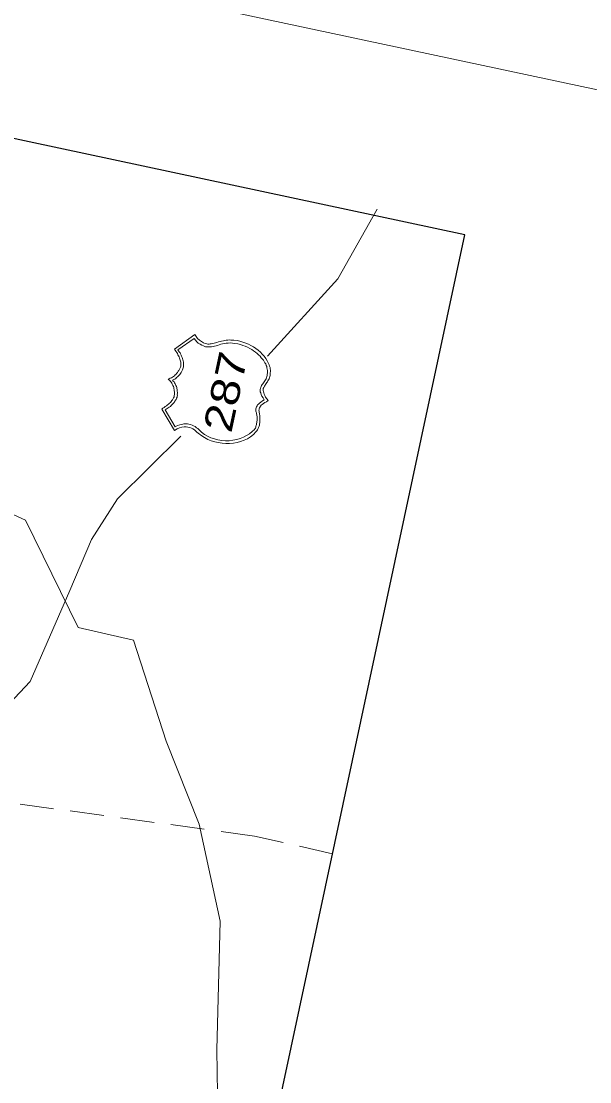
# Model space of a CAD drawing. Extents: x 2363411 to 2369126, y 6976878 to 6988319.
# Drawn here: x 2366148.5 to 2366249.3, y 6977167 to 6977355.3 of the extents above; entities that cross this region are included whole.
import ezdxf

# ---------------------------------------------------------------- set-up
doc = ezdxf.new("R2010")
doc.units = 0
doc.header["$LTSCALE"] = 2
doc.linetypes.add('MEDIUM_DASHED', pattern=[4.5, 3, -1.5])
for name, color, linetype, lineweight in [('44', 7, 'Continuous', 40), ('62', 7, 'Continuous', 13), ('63', 7, 'Continuous', 13)]:
    doc.layers.add(name, color=color, linetype=linetype, lineweight=lineweight)

msp = doc.modelspace()

# ---------------------------------------------------------------- linework, layer by layer
at = {"layer": '44', "lineweight": 13}
msp.add_line((2363411.416, 6977949.748), (2366932.108, 6977197.487), dxfattribs=at)
at = {"layer": '62'}
for p, q in [((2366211.587, 6977321.915), (2366204.664, 6977309.563)), ((2366204.664, 6977309.563), (2366192.137, 6977295.834)), ((2366165.563, 6977270.54), (2366176.769, 6977281.631))]:
    msp.add_line(p, q, dxfattribs=at)
at = {"layer": '62', "lineweight": 25}
msp.add_lwpolyline([(2365678.211, 6976974.92), (2366133.213, 6976877.7), (2366227.156, 6977317.368), (2365772.152, 6977414.588)], dxfattribs=at)
at = {"layer": '62'}
for points in [[(2366096.932, 6977302.67), (2366104.486, 6977295.374), (2366118.795, 6977282.65), (2366135.856, 6977272.793), (2366149.213, 6977266.718), (2366158.553, 6977247.649), (2366168.364, 6977245.412), (2366174.148, 6977227.473), (2366180.022, 6977212.757), (2366183.73, 6977195.536), (2366183.185, 6977172.733), (2366183.468, 6977153.162), (2366184.402, 6977131.701), (2366184.733, 6977118.813)], [(2366175.627, 6977282.636), (2366173.381, 6977286.45), (2366173.595, 6977286.59), (2366173.831, 6977286.722), (2366174.026, 6977286.886), (2366174.236, 6977287.003), (2366174.432, 6977287.172), (2366174.603, 6977287.317), (2366174.771, 6977287.466), (2366174.946, 6977287.635), (2366175.068, 6977287.77), (2366175.197, 6977287.949), (2366175.324, 6977288.106), (2366175.411, 6977288.296), (2366175.492, 6977288.463), (2366175.566, 6977288.607), (2366175.616, 6977288.827), (2366175.658, 6977289.025), (2366175.642, 6977289.167), (2366175.629, 6977289.329), (2366175.645, 6977289.51), (2366175.617, 6977289.7), (2366175.589, 6977289.892), (2366175.534, 6977290.064), (2366175.506, 6977290.256), (2366175.456, 6977290.448), (2366175.357, 6977290.631), (2366175.263, 6977290.835), (2366175.164, 6977291.018), (2366175.087, 6977291.194), (2366174.954, 6977291.339), (2366174.83, 6977291.502), (2366174.646, 6977291.611), (2366174.515, 6977291.754), (2366174.691, 6977291.831), (2366174.914, 6977291.9), (2366175.118, 6977291.993), (2366175.28, 6977292.097), (2366175.467, 6977292.219), (2366175.636, 6977292.365), (2366175.777, 6977292.496), (2366175.926, 6977292.649), (2366176.072, 6977292.799), (2366176.215, 6977292.932), (2366176.308, 6977293.142), (2366176.428, 6977293.28), (2366176.525, 6977293.511), (2366176.601, 6977293.656), (2366176.693, 6977293.865), (2366176.752, 6977294.039), (2366176.784, 6977294.191), (2366176.803, 6977294.394), (2366176.767, 6977294.541), (2366176.766, 6977294.745), (2366176.736, 6977294.938), (2366176.681, 6977295.111), (2366176.628, 6977295.284), (2366176.558, 6977295.506), (2366176.459, 6977295.688), (2366176.388, 6977295.886), (2366176.266, 6977296.073), (2366176.176, 6977296.299), (2366176.057, 6977296.488), (2366175.916, 6977296.7), (2366175.773, 6977296.892), (2366175.657, 6977297.101), (2366179.266, 6977299.668), (2366179.513, 6977299.314), (2366179.759, 6977298.963), (2366180.09, 6977298.684), (2366180.454, 6977298.446), (2366180.796, 6977298.212), (2366181.111, 6977298.073), (2366181.397, 6977298.014), (2366181.595, 6977297.972), (2366181.782, 6977297.979), (2366181.992, 6977298.003), (2366182.184, 6977298.03), (2366182.422, 6977298.071), (2366182.664, 6977298.134), (2366182.909, 6977298.198), (2366183.179, 6977298.279), (2366183.449, 6977298.359), (2366183.743, 6977298.433), (2366184.012, 6977298.515), (2366184.323, 6977298.563), (2366184.588, 6977298.62), (2366184.849, 6977298.657), (2366185.108, 6977298.693), (2366185.387, 6977298.703), (2366185.637, 6977298.695), (2366186.203, 6977298.644), (2366186.768, 6977298.594), (2366187.273, 6977298.484), (2366187.786, 6977298.305), (2366188.305, 6977298.149), (2366188.772, 6977297.958), (2366189.227, 6977297.721), (2366189.677, 6977297.464), (2366190.106, 6977297.212), (2366190.522, 6977296.892)], [(2366191.02, 6977295.567), (2366190.844, 6977295.811), (2366190.573, 6977296.055), (2366190.303, 6977296.295), (2366190.01, 6977296.542), (2366189.692, 6977296.771), (2366189.35, 6977297.006), (2366189.005, 6977297.219), (2366188.608, 6977297.416), (2366188.193, 6977297.621), (2366187.784, 6977297.754), (2366187.336, 6977297.917), (2366186.873, 6977298.02), (2366186.386, 6977298.099), (2366185.957, 6977298.144), (2366185.553, 6977298.185), (2366185.2, 6977298.146), (2366184.829, 6977298.131), (2366184.491, 6977298.067), (2366184.182, 6977298.018), (2366183.868, 6977297.946), (2366183.572, 6977297.848), (2366183.274, 6977297.752), (2366183.025, 6977297.666), (2366182.76, 6977297.608), (2366182.495, 6977297.55), (2366182.208, 6977297.495), (2366181.974, 6977297.477), (2366181.716, 6977297.463), (2366181.443, 6977297.474), (2366181.13, 6977297.519), (2366180.814, 6977297.656), (2366180.498, 6977297.793), (2366180.187, 6977297.951), (2366179.864, 6977298.157), (2366179.615, 6977298.395), (2366179.375, 6977298.677), (2366179.136, 6977298.957), (2366176.246, 6977296.953), (2366176.368, 6977296.767), (2366176.494, 6977296.599), (2366176.637, 6977296.409), (2366176.737, 6977296.226), (2366176.852, 6977296.019), (2366176.924, 6977295.818), (2366176.997, 6977295.62), (2366177.07, 6977295.419), (2366177.137, 6977295.198), (2366177.209, 6977294.998), (2366177.233, 6977294.785), (2366177.239, 6977294.601), (2366177.269, 6977294.409), (2366177.257, 6977294.252), (2366177.247, 6977294.095), (2366177.237, 6977293.933), (2366177.181, 6977293.786), (2366177.12, 6977293.612), (2366177.079, 6977293.417), (2366177.001, 6977293.27), (2366176.888, 6977293.065), (2366176.812, 6977292.92), (2366176.707, 6977292.758), (2366176.579, 6977292.579), (2366176.456, 6977292.443), (2366176.326, 6977292.265), (2366176.189, 6977292.157), (2366176.022, 6977292.031), (2366175.875, 6977291.878), (2366175.693, 6977291.78), (2366175.512, 6977291.68), (2366175.307, 6977291.587), (2366175.432, 6977291.421), (2366175.58, 6977291.252), (2366175.662, 6977291.095), (2366175.766, 6977290.934), (2366175.821, 6977290.763), (2366175.907, 6977290.628), (2366175.981, 6977290.428), (2366176.04, 6977290.279), (2366176.074, 6977290.11), (2366176.125, 6977289.915), (2366176.14, 6977289.772), (2366176.145, 6977289.589), (2366176.157, 6977289.425), (2366176.19, 6977289.256), (2366176.152, 6977289.081), (2366176.163, 6977288.919), (2366176.153, 6977288.757), (2366176.105, 6977288.539), (2366175.997, 6977288.355), (2366175.927, 6977288.139), (2366175.801, 6977287.982), (2366175.69, 6977287.774), (2366175.554, 6977287.576), (2366175.41, 6977287.443), (2366175.254, 6977287.248), (2366175.08, 6977287.078), (2366174.932, 6977286.926), (2366174.721, 6977286.807), (2366174.549, 6977286.64), (2366174.34, 6977286.521)], [(2366174.02, 6977286.315), (2366175.794, 6977283.312), (2366176.204, 6977283.501), (2366176.603, 6977283.644), (2366176.965, 6977283.729), (2366177.305, 6977283.818), (2366177.649, 6977283.812), (2366177.949, 6977283.817), (2366178.217, 6977283.782), (2366178.522, 6977283.697), (2366178.795, 6977283.569), (2366179.048, 6977283.468), (2366179.295, 6977283.323), (2366179.531, 6977283.133), (2366179.77, 6977282.97), (2366180.005, 6977282.78), (2366180.216, 6977282.576), (2366180.446, 6977282.363), (2366180.956, 6977281.956), (2366181.532, 6977281.626), (2366182.092, 6977281.345), (2366182.737, 6977281.137), (2366183.371, 6977280.979), (2366184.035, 6977280.86), (2366184.72, 6977280.828), (2366185.364, 6977280.83), (2366186.022, 6977280.895), (2366186.695, 6977281.028), (2366187.313, 6977281.219), (2366187.911, 6977281.437), (2366188.455, 6977281.734), (2366188.985, 6977282.058), (2366189.437, 6977282.444), (2366189.843, 6977282.84), (2366189.91, 6977282.94), (2366190.006, 6977283.059), (2366190.059, 6977283.209), (2366190.097, 6977283.385), (2366190.147, 6977283.511), (2366190.186, 6977283.689), (2366190.224, 6977283.865), (2366190.261, 6977284.041), (2366190.282, 6977284.243), (2366190.313, 6977284.398), (2366190.313, 6977284.603), (2366190.327, 6977284.786), (2366190.318, 6977284.949), (2366190.311, 6977285.135), (2366190.277, 6977285.304), (2366190.283, 6977285.44), (2366190.224, 6977285.591), (2366190.189, 6977285.758), (2366190.15, 6977285.883), (2366190.114, 6977286.05), (2366190.104, 6977286.214), (2366190.111, 6977286.352), (2366190.1, 6977286.513), (2366190.131, 6977286.668), (2366190.208, 6977286.813), (2366190.295, 6977287.004), (2366190.376, 6977287.168), (2366190.545, 6977287.314), (2366190.725, 6977287.509), (2366190.992, 6977287.681), (2366191.268, 6977287.898), (2366191.585, 6977288.084), (2366191.359, 6977288.431), (2366191.174, 6977288.746), (2366191.05, 6977289.024), (2366190.948, 6977289.302), (2366190.879, 6977289.523), (2366190.878, 6977289.73), (2366190.871, 6977289.915), (2366190.918, 6977290.136), (2366190.951, 6977290.291), (2366191.028, 6977290.434), (2366191.114, 6977290.622), (2366191.217, 6977290.784), (2366191.339, 6977290.922), (2366191.441, 6977291.082), (2366191.552, 6977291.265), (2366191.683, 6977291.446), (2366191.791, 6977291.629), (2366191.897, 6977291.811), (2366191.963, 6977292.005), (2366192.009, 6977292.227), (2366192.074, 6977292.421), (2366192.1, 6977292.645), (2366192.141, 6977292.843), (2366192.144, 6977293.071), (2366192.148, 6977293.301), (2366192.124, 6977293.513), (2366192.061, 6977293.758), (2366192.015, 6977293.974), (2366191.925, 6977294.2), (2366191.841, 6977294.449), (2366191.702, 6977294.663), (2366191.545, 6977294.903), (2366191.43, 6977295.111), (2366191.225, 6977295.339), (2366191.02, 6977295.567)], [(2366190.522, 6977296.892), (2366190.887, 6977296.561), (2366191.201, 6977296.195), (2366191.564, 6977295.842), (2366191.834, 6977295.391), (2366192.117, 6977294.987), (2366192.341, 6977294.526), (2366192.447, 6977294.272), (2366192.537, 6977294.049), (2366192.599, 6977293.802), (2366192.64, 6977293.564), (2366192.687, 6977293.348), (2366192.661, 6977293.122), (2366192.655, 6977292.87), (2366192.655, 6977292.665), (2366192.603, 6977292.421), (2366192.556, 6977292.2), (2366192.491, 6977292.009), (2366192.432, 6977291.838), (2366192.319, 6977291.633), (2366192.238, 6977291.464), (2366192.157, 6977291.297), (2366192.03, 6977291.14), (2366191.927, 6977290.98), (2366191.824, 6977290.816), (2366191.729, 6977290.7), (2366191.627, 6977290.537), (2366191.575, 6977290.409), (2366191.493, 6977290.243), (2366191.412, 6977290.078), (2366191.402, 6977289.917), (2366191.409, 6977289.731), (2366191.431, 6977289.52), (2366191.504, 6977289.32), (2366191.571, 6977289.099), (2366191.678, 6977288.845), (2366191.829, 6977288.584), (2366192.041, 6977288.285), (2366192.27, 6977287.96), (2366191.95, 6977287.75), (2366191.684, 6977287.58), (2366191.421, 6977287.428), (2366191.22, 6977287.241), (2366191.057, 6977287.115), (2366190.932, 6977286.958), (2366190.83, 6977286.818), (2366190.755, 6977286.674), (2366190.703, 6977286.546), (2366190.671, 6977286.391), (2366190.643, 6977286.26), (2366190.654, 6977286.099), (2366190.674, 6977285.98), (2366190.664, 6977285.818), (2366190.719, 6977285.647), (2366190.734, 6977285.505), (2366190.772, 6977285.36), (2366190.784, 6977285.195), (2366190.811, 6977285.006), (2366190.813, 6977284.797), (2366190.819, 6977284.611), (2366190.799, 6977284.409), (2366190.803, 6977284.202), (2366190.809, 6977284.018), (2366190.76, 6977283.798), (2366190.718, 6977283.598), (2366190.676, 6977283.398), (2366190.582, 6977283.167), (2366190.494, 6977282.977), (2366190.381, 6977282.772), (2366190.246, 6977282.572), (2366190.088, 6977282.375), (2366189.65, 6977281.938), (2366189.128, 6977281.543), (2366188.59, 6977281.175), (2366188.003, 6977280.91), (2366187.38, 6977280.675), (2366186.745, 6977280.512), (2366186.105, 6977280.42), (2366185.424, 6977280.357), (2366184.754, 6977280.338), (2366184.096, 6977280.387), (2366183.426, 6977280.485), (2366182.787, 6977280.619), (2366182.162, 6977280.823), (2366181.574, 6977281.065), (2366180.993, 6977281.373), (2366180.49, 6977281.709), (2366180.288, 6977281.845), (2366180.07, 6977282.006), (2366179.878, 6977282.186), (2366179.644, 6977282.373), (2366179.409, 6977282.564), (2366179.173, 6977282.75), (2366178.931, 6977282.918), (2366178.66, 6977283.043), (2366178.366, 6977283.176), (2366178.035, 6977283.248), (2366177.701, 6977283.295), (2366177.351, 6977283.278), (2366176.949, 6977283.227), (2366176.533, 6977283.107)], [(2366174.34, 6977286.521), (2366174.181, 6977286.418), (2366174.02, 6977286.315)], [(2366176.533, 6977283.107), (2366176.103, 6977282.923), (2366175.627, 6977282.636)], [(2366165.563, 6977270.54), (2366160.925, 6977263.273), (2366157.11, 6977254.238), (2366150.016, 6977238.06), (2366141.756, 6977229.335), (2366136.001, 6977223.497), (2366128.351, 6977216.018), (2366117.334, 6977209.377), (2366106.082, 6977205.501), (2366093.663, 6977202.078), (2366078.646, 6977196.636), (2366068.712, 6977191.165), (2366059.206, 6977187.374), (2366047.443, 6977183.467), (2366041.833, 6977180.594), (2366027.902, 6977176.345)]]:
    msp.add_lwpolyline(points, dxfattribs=at)
at = {"layer": '62', "linetype": 'MEDIUM_DASHED'}
msp.add_lwpolyline([(2366203.686, 6977207.519), (2366189.861, 6977210.657), (2366146.236, 6977216.593), (2366117.386, 6977222.114)], dxfattribs=at)
at = {"layer": '63'}
for p, q in [((2366211.587, 6977321.915), (2366204.664, 6977309.563)), ((2366204.664, 6977309.563), (2366192.137, 6977295.834)), ((2366165.563, 6977270.54), (2366176.769, 6977281.631))]:
    msp.add_line(p, q, dxfattribs=at)
at = {"layer": '63', "lineweight": 25}
msp.add_lwpolyline([(2365678.211, 6976974.92), (2366133.213, 6976877.7), (2366227.156, 6977317.368), (2365772.152, 6977414.588)], dxfattribs=at)
at = {"layer": '63'}
for points in [[(2366096.932, 6977302.67), (2366104.486, 6977295.374), (2366118.795, 6977282.65), (2366135.856, 6977272.793), (2366149.213, 6977266.718), (2366158.553, 6977247.649), (2366168.364, 6977245.412), (2366174.148, 6977227.473), (2366180.022, 6977212.757), (2366183.73, 6977195.536), (2366183.185, 6977172.733), (2366183.468, 6977153.162), (2366184.402, 6977131.701), (2366184.733, 6977118.813)], [(2366175.627, 6977282.636), (2366173.381, 6977286.45), (2366173.595, 6977286.59), (2366173.831, 6977286.722), (2366174.026, 6977286.886), (2366174.236, 6977287.003), (2366174.432, 6977287.172), (2366174.603, 6977287.317), (2366174.771, 6977287.466), (2366174.946, 6977287.635), (2366175.068, 6977287.77), (2366175.197, 6977287.949), (2366175.324, 6977288.106), (2366175.411, 6977288.296), (2366175.492, 6977288.463), (2366175.566, 6977288.607), (2366175.616, 6977288.827), (2366175.658, 6977289.025), (2366175.642, 6977289.167), (2366175.629, 6977289.329), (2366175.645, 6977289.51), (2366175.617, 6977289.7), (2366175.589, 6977289.892), (2366175.534, 6977290.064), (2366175.506, 6977290.256), (2366175.456, 6977290.448), (2366175.357, 6977290.631), (2366175.263, 6977290.835), (2366175.164, 6977291.018), (2366175.087, 6977291.194), (2366174.954, 6977291.339), (2366174.83, 6977291.502), (2366174.646, 6977291.611), (2366174.515, 6977291.754), (2366174.691, 6977291.831), (2366174.914, 6977291.9), (2366175.118, 6977291.993), (2366175.28, 6977292.097), (2366175.467, 6977292.219), (2366175.636, 6977292.365), (2366175.777, 6977292.496), (2366175.926, 6977292.649), (2366176.072, 6977292.799), (2366176.215, 6977292.932), (2366176.308, 6977293.142), (2366176.428, 6977293.28), (2366176.525, 6977293.511), (2366176.601, 6977293.656), (2366176.693, 6977293.865), (2366176.752, 6977294.039), (2366176.784, 6977294.191), (2366176.803, 6977294.394), (2366176.767, 6977294.541), (2366176.766, 6977294.745), (2366176.736, 6977294.938), (2366176.681, 6977295.111), (2366176.628, 6977295.284), (2366176.558, 6977295.506), (2366176.459, 6977295.688), (2366176.388, 6977295.886), (2366176.266, 6977296.073), (2366176.176, 6977296.299), (2366176.057, 6977296.488), (2366175.916, 6977296.7), (2366175.773, 6977296.892), (2366175.657, 6977297.101), (2366179.266, 6977299.668), (2366179.513, 6977299.314), (2366179.759, 6977298.963), (2366180.09, 6977298.684), (2366180.454, 6977298.446), (2366180.796, 6977298.212), (2366181.111, 6977298.073), (2366181.397, 6977298.014), (2366181.595, 6977297.972), (2366181.782, 6977297.979), (2366181.992, 6977298.003), (2366182.184, 6977298.03), (2366182.422, 6977298.071), (2366182.664, 6977298.134), (2366182.909, 6977298.198), (2366183.179, 6977298.279), (2366183.449, 6977298.359), (2366183.743, 6977298.433), (2366184.012, 6977298.515), (2366184.323, 6977298.563), (2366184.588, 6977298.62), (2366184.849, 6977298.657), (2366185.108, 6977298.693), (2366185.387, 6977298.703), (2366185.637, 6977298.695), (2366186.203, 6977298.644), (2366186.768, 6977298.594), (2366187.273, 6977298.484), (2366187.786, 6977298.305), (2366188.305, 6977298.149), (2366188.772, 6977297.958), (2366189.227, 6977297.721), (2366189.677, 6977297.464), (2366190.106, 6977297.212), (2366190.522, 6977296.892)], [(2366191.02, 6977295.567), (2366190.844, 6977295.811), (2366190.573, 6977296.055), (2366190.303, 6977296.295), (2366190.01, 6977296.542), (2366189.692, 6977296.771), (2366189.35, 6977297.006), (2366189.005, 6977297.219), (2366188.608, 6977297.416), (2366188.193, 6977297.621), (2366187.784, 6977297.754), (2366187.336, 6977297.917), (2366186.873, 6977298.02), (2366186.386, 6977298.099), (2366185.957, 6977298.144), (2366185.553, 6977298.185), (2366185.2, 6977298.146), (2366184.829, 6977298.131), (2366184.491, 6977298.067), (2366184.182, 6977298.018), (2366183.868, 6977297.946), (2366183.572, 6977297.848), (2366183.274, 6977297.752), (2366183.025, 6977297.666), (2366182.76, 6977297.608), (2366182.495, 6977297.55), (2366182.208, 6977297.495), (2366181.974, 6977297.477), (2366181.716, 6977297.463), (2366181.443, 6977297.474), (2366181.13, 6977297.519), (2366180.814, 6977297.656), (2366180.498, 6977297.793), (2366180.187, 6977297.951), (2366179.864, 6977298.157), (2366179.615, 6977298.395), (2366179.375, 6977298.677), (2366179.136, 6977298.957), (2366176.246, 6977296.953), (2366176.368, 6977296.767), (2366176.494, 6977296.599), (2366176.637, 6977296.409), (2366176.737, 6977296.226), (2366176.852, 6977296.019), (2366176.924, 6977295.818), (2366176.997, 6977295.62), (2366177.07, 6977295.419), (2366177.137, 6977295.198), (2366177.209, 6977294.998), (2366177.233, 6977294.785), (2366177.239, 6977294.601), (2366177.269, 6977294.409), (2366177.257, 6977294.252), (2366177.247, 6977294.095), (2366177.237, 6977293.933), (2366177.181, 6977293.786), (2366177.12, 6977293.612), (2366177.079, 6977293.417), (2366177.001, 6977293.27), (2366176.888, 6977293.065), (2366176.812, 6977292.92), (2366176.707, 6977292.758), (2366176.579, 6977292.579), (2366176.456, 6977292.443), (2366176.326, 6977292.265), (2366176.189, 6977292.157), (2366176.022, 6977292.031), (2366175.875, 6977291.878), (2366175.693, 6977291.78), (2366175.512, 6977291.68), (2366175.307, 6977291.587), (2366175.432, 6977291.421), (2366175.58, 6977291.252), (2366175.662, 6977291.095), (2366175.766, 6977290.934), (2366175.821, 6977290.763), (2366175.907, 6977290.628), (2366175.981, 6977290.428), (2366176.04, 6977290.279), (2366176.074, 6977290.11), (2366176.125, 6977289.915), (2366176.14, 6977289.772), (2366176.145, 6977289.589), (2366176.157, 6977289.425), (2366176.19, 6977289.256), (2366176.152, 6977289.081), (2366176.163, 6977288.919), (2366176.153, 6977288.757), (2366176.105, 6977288.539), (2366175.997, 6977288.355), (2366175.927, 6977288.139), (2366175.801, 6977287.982), (2366175.69, 6977287.774), (2366175.554, 6977287.576), (2366175.41, 6977287.443), (2366175.254, 6977287.248), (2366175.08, 6977287.078), (2366174.932, 6977286.926), (2366174.721, 6977286.807), (2366174.549, 6977286.64), (2366174.34, 6977286.521)], [(2366174.02, 6977286.315), (2366175.794, 6977283.312), (2366176.204, 6977283.501), (2366176.603, 6977283.644), (2366176.965, 6977283.729), (2366177.305, 6977283.818), (2366177.649, 6977283.812), (2366177.949, 6977283.817), (2366178.217, 6977283.782), (2366178.522, 6977283.697), (2366178.795, 6977283.569), (2366179.048, 6977283.468), (2366179.295, 6977283.323), (2366179.531, 6977283.133), (2366179.77, 6977282.97), (2366180.005, 6977282.78), (2366180.216, 6977282.576), (2366180.446, 6977282.363), (2366180.956, 6977281.956), (2366181.532, 6977281.626), (2366182.092, 6977281.345), (2366182.737, 6977281.137), (2366183.371, 6977280.979), (2366184.035, 6977280.86), (2366184.72, 6977280.828), (2366185.364, 6977280.83), (2366186.022, 6977280.895), (2366186.695, 6977281.028), (2366187.313, 6977281.219), (2366187.911, 6977281.437), (2366188.455, 6977281.734), (2366188.985, 6977282.058), (2366189.437, 6977282.444), (2366189.843, 6977282.84), (2366189.91, 6977282.94), (2366190.006, 6977283.059), (2366190.059, 6977283.209), (2366190.097, 6977283.385), (2366190.147, 6977283.511), (2366190.186, 6977283.689), (2366190.224, 6977283.865), (2366190.261, 6977284.041), (2366190.282, 6977284.243), (2366190.313, 6977284.398), (2366190.313, 6977284.603), (2366190.327, 6977284.786), (2366190.318, 6977284.949), (2366190.311, 6977285.135), (2366190.277, 6977285.304), (2366190.283, 6977285.44), (2366190.224, 6977285.591), (2366190.189, 6977285.758), (2366190.15, 6977285.883), (2366190.114, 6977286.05), (2366190.104, 6977286.214), (2366190.111, 6977286.352), (2366190.1, 6977286.513), (2366190.131, 6977286.668), (2366190.208, 6977286.813), (2366190.295, 6977287.004), (2366190.376, 6977287.168), (2366190.545, 6977287.314), (2366190.725, 6977287.509), (2366190.992, 6977287.681), (2366191.268, 6977287.898), (2366191.585, 6977288.084), (2366191.359, 6977288.431), (2366191.174, 6977288.746), (2366191.05, 6977289.024), (2366190.948, 6977289.302), (2366190.879, 6977289.523), (2366190.878, 6977289.73), (2366190.871, 6977289.915), (2366190.918, 6977290.136), (2366190.951, 6977290.291), (2366191.028, 6977290.434), (2366191.114, 6977290.622), (2366191.217, 6977290.784), (2366191.339, 6977290.922), (2366191.441, 6977291.082), (2366191.552, 6977291.265), (2366191.683, 6977291.446), (2366191.791, 6977291.629), (2366191.897, 6977291.811), (2366191.963, 6977292.005), (2366192.009, 6977292.227), (2366192.074, 6977292.421), (2366192.1, 6977292.645), (2366192.141, 6977292.843), (2366192.144, 6977293.071), (2366192.148, 6977293.301), (2366192.124, 6977293.513), (2366192.061, 6977293.758), (2366192.015, 6977293.974), (2366191.925, 6977294.2), (2366191.841, 6977294.449), (2366191.702, 6977294.663), (2366191.545, 6977294.903), (2366191.43, 6977295.111), (2366191.225, 6977295.339), (2366191.02, 6977295.567)], [(2366190.522, 6977296.892), (2366190.887, 6977296.561), (2366191.201, 6977296.195), (2366191.564, 6977295.842), (2366191.834, 6977295.391), (2366192.117, 6977294.987), (2366192.341, 6977294.526), (2366192.447, 6977294.272), (2366192.537, 6977294.049), (2366192.599, 6977293.802), (2366192.64, 6977293.564), (2366192.687, 6977293.348), (2366192.661, 6977293.122), (2366192.655, 6977292.87), (2366192.655, 6977292.665), (2366192.603, 6977292.421), (2366192.556, 6977292.2), (2366192.491, 6977292.009), (2366192.432, 6977291.838), (2366192.319, 6977291.633), (2366192.238, 6977291.464), (2366192.157, 6977291.297), (2366192.03, 6977291.14), (2366191.927, 6977290.98), (2366191.824, 6977290.816), (2366191.729, 6977290.7), (2366191.627, 6977290.537), (2366191.575, 6977290.409), (2366191.493, 6977290.243), (2366191.412, 6977290.078), (2366191.402, 6977289.917), (2366191.409, 6977289.731), (2366191.431, 6977289.52), (2366191.504, 6977289.32), (2366191.571, 6977289.099), (2366191.678, 6977288.845), (2366191.829, 6977288.584), (2366192.041, 6977288.285), (2366192.27, 6977287.96), (2366191.95, 6977287.75), (2366191.684, 6977287.58), (2366191.421, 6977287.428), (2366191.22, 6977287.241), (2366191.057, 6977287.115), (2366190.932, 6977286.958), (2366190.83, 6977286.818), (2366190.755, 6977286.674), (2366190.703, 6977286.546), (2366190.671, 6977286.391), (2366190.643, 6977286.26), (2366190.654, 6977286.099), (2366190.674, 6977285.98), (2366190.664, 6977285.818), (2366190.719, 6977285.647), (2366190.734, 6977285.505), (2366190.772, 6977285.36), (2366190.784, 6977285.195), (2366190.811, 6977285.006), (2366190.813, 6977284.797), (2366190.819, 6977284.611), (2366190.799, 6977284.409), (2366190.803, 6977284.202), (2366190.809, 6977284.018), (2366190.76, 6977283.798), (2366190.718, 6977283.598), (2366190.676, 6977283.398), (2366190.582, 6977283.167), (2366190.494, 6977282.977), (2366190.381, 6977282.772), (2366190.246, 6977282.572), (2366190.088, 6977282.375), (2366189.65, 6977281.938), (2366189.128, 6977281.543), (2366188.59, 6977281.175), (2366188.003, 6977280.91), (2366187.38, 6977280.675), (2366186.745, 6977280.512), (2366186.105, 6977280.42), (2366185.424, 6977280.357), (2366184.754, 6977280.338), (2366184.096, 6977280.387), (2366183.426, 6977280.485), (2366182.787, 6977280.619), (2366182.162, 6977280.823), (2366181.574, 6977281.065), (2366180.993, 6977281.373), (2366180.49, 6977281.709), (2366180.288, 6977281.845), (2366180.07, 6977282.006), (2366179.878, 6977282.186), (2366179.644, 6977282.373), (2366179.409, 6977282.564), (2366179.173, 6977282.75), (2366178.931, 6977282.918), (2366178.66, 6977283.043), (2366178.366, 6977283.176), (2366178.035, 6977283.248), (2366177.701, 6977283.295), (2366177.351, 6977283.278), (2366176.949, 6977283.227), (2366176.533, 6977283.107)], [(2366174.34, 6977286.521), (2366174.181, 6977286.418), (2366174.02, 6977286.315)], [(2366176.533, 6977283.107), (2366176.103, 6977282.923), (2366175.627, 6977282.636)], [(2366165.563, 6977270.54), (2366160.925, 6977263.273), (2366157.11, 6977254.238), (2366150.016, 6977238.06), (2366141.756, 6977229.335), (2366136.001, 6977223.497), (2366128.351, 6977216.018), (2366117.334, 6977209.377), (2366106.082, 6977205.501), (2366093.663, 6977202.078), (2366078.646, 6977196.636), (2366068.712, 6977191.165), (2366059.206, 6977187.374), (2366047.443, 6977183.467), (2366041.833, 6977180.594), (2366027.902, 6977176.345)]]:
    msp.add_lwpolyline(points, dxfattribs=at)
at = {"layer": '63', "linetype": 'MEDIUM_DASHED'}
msp.add_lwpolyline([(2366203.686, 6977207.519), (2366189.861, 6977210.657), (2366146.236, 6977216.593), (2366117.386, 6977222.114)], dxfattribs=at)

# ---------------------------------------------------------------- texts
at = {"layer": '62', "width": 1.25}
msp.add_text('287', height=5.099, rotation=77.939, dxfattribs=at).set_placement((2366185.711, 6977282.021))
at = {"layer": '63', "width": 1.25}
msp.add_text('287', height=5.099, rotation=77.939, dxfattribs=at).set_placement((2366185.711, 6977282.021))

doc.saveas('drawing.dxf')
